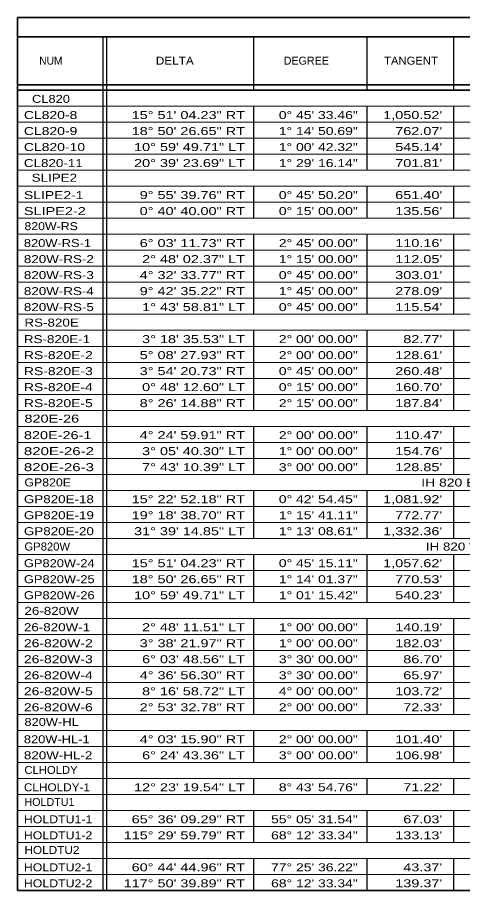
# Model space of a CAD drawing. Extents: x 1953053 to 1967065, y 7363860 to 7371201.
# Drawn here: x 1961966 to 1962633, y 7368856 to 7370165 of the extents above; entities that cross this region are included whole.
import ezdxf
from ezdxf.enums import TextEntityAlignment as Align

# ---------------------------------------------------------------- set-up
doc = ezdxf.new("R2010")
doc.units = 0
doc.header["$LTSCALE"] = 4.8
doc.layers.add('10', color=7, linetype='Continuous')
doc.layers.add('12', color=7, linetype='Continuous', lineweight=25)

msp = doc.modelspace()

# ---------------------------------------------------------------- linework, layer by layer
at = {"layer": '12', "lineweight": 35}
for p, q in [((1963689.794, 7370164.879), (1961966.462, 7370164.879)), ((1961966.462, 7370164.879), (1961966.462, 7368855.748)), ((1961966.462, 7370136.079), (1963689.794, 7370136.079)), ((1961966.462, 7370064.079), (1963689.794, 7370064.079)), ((1961966.462, 7370055.746), (1963689.794, 7370055.746)), ((1961966.462, 7368855.748), (1963689.794, 7368855.748))]:
    msp.add_line(p, q, dxfattribs=at)
at = {"layer": '12'}
for p, q in [((1962094.307, 7370136.079), (1962094.307, 7368855.748)), ((1962099.794, 7370136.079), (1962099.794, 7368855.748)), ((1962319.794, 7370136.079), (1962319.794, 7370055.746)), ((1962489.794, 7370136.079), (1962489.794, 7370055.746)), ((1962619.794, 7370136.079), (1962619.794, 7370055.746)), ((1962094.307, 7370114.479), (1962094.307, 7369766.526)), ((1962319.794, 7370031.746), (1962319.794, 7369935.746)), ((1962489.794, 7370031.746), (1962489.794, 7369935.746)), ((1962619.794, 7370031.746), (1962619.794, 7369935.746)), ((1962319.794, 7369911.746), (1962319.794, 7369863.746)), ((1962489.794, 7369911.746), (1962489.794, 7369863.746)), ((1962619.794, 7369911.746), (1962619.794, 7369863.746)), ((1962319.794, 7369839.746), (1962319.794, 7369719.746)), ((1962489.794, 7369839.746), (1962489.794, 7369719.746)), ((1962619.794, 7369839.746), (1962619.794, 7369719.746)), ((1962319.794, 7369695.746), (1962319.794, 7369575.746)), ((1962489.794, 7369695.746), (1962489.794, 7369575.746)), ((1962619.794, 7369695.746), (1962619.794, 7369575.746)), ((1962319.794, 7369551.746), (1962319.794, 7369479.746)), ((1962489.794, 7369551.746), (1962489.794, 7369479.746)), ((1962619.794, 7369551.746), (1962619.794, 7369479.746)), ((1962319.794, 7369455.746), (1962319.794, 7369383.746)), ((1962489.794, 7369455.746), (1962489.794, 7369383.746)), ((1962619.794, 7369455.746), (1962619.794, 7369383.746)), ((1962319.794, 7369359.746), (1962319.794, 7369287.746)), ((1962489.794, 7369359.746), (1962489.794, 7369287.746)), ((1962619.794, 7369359.746), (1962619.794, 7369287.746)), ((1962319.794, 7369263.746), (1962319.794, 7369119.746)), ((1962489.794, 7369263.746), (1962489.794, 7369119.746)), ((1962619.794, 7369263.746), (1962619.794, 7369119.746)), ((1962319.794, 7369095.746), (1962319.794, 7369047.747)), ((1962489.794, 7369095.746), (1962489.794, 7369047.747)), ((1962619.794, 7369095.746), (1962619.794, 7369047.747)), ((1962319.794, 7369023.747), (1962319.794, 7368999.747)), ((1962489.794, 7369023.747), (1962489.794, 7368999.747)), ((1962619.794, 7369023.747), (1962619.794, 7368999.747)), ((1962319.794, 7368975.747), (1962319.794, 7368927.747)), ((1962489.794, 7368975.747), (1962489.794, 7368927.747)), ((1962619.794, 7368975.747), (1962619.794, 7368927.747)), ((1962319.794, 7368903.747), (1962319.794, 7368855.747)), ((1962489.794, 7368903.747), (1962489.794, 7368855.747)), ((1962619.794, 7368903.747), (1962619.794, 7368855.747))]:
    msp.add_line(p, q, dxfattribs=at)
at = {"layer": '12', "lineweight": 13}
for p, q in [((1961966.462, 7370031.746), (1963689.794, 7370031.746)), ((1961966.462, 7370007.746), (1963689.794, 7370007.746)), ((1961966.462, 7369983.746), (1963689.794, 7369983.746)), ((1961966.462, 7369959.746), (1963689.794, 7369959.746)), ((1961966.462, 7369935.746), (1963689.794, 7369935.746)), ((1961966.462, 7369911.746), (1963689.794, 7369911.746)), ((1961966.462, 7369887.746), (1963689.794, 7369887.746)), ((1961966.462, 7369863.746), (1963689.794, 7369863.746)), ((1961966.462, 7369839.746), (1963689.794, 7369839.746)), ((1961966.462, 7369815.746), (1963689.794, 7369815.746)), ((1961966.462, 7369791.746), (1963689.794, 7369791.746)), ((1961966.462, 7369767.746), (1963689.794, 7369767.746)), ((1961966.462, 7369743.746), (1963689.794, 7369743.746)), ((1961966.462, 7369719.746), (1963689.794, 7369719.746)), ((1961966.462, 7369695.746), (1963689.794, 7369695.746)), ((1961966.462, 7369671.746), (1963689.794, 7369671.746)), ((1961966.462, 7369647.746), (1963689.794, 7369647.746)), ((1961966.462, 7369623.746), (1963689.794, 7369623.746)), ((1961966.462, 7369599.746), (1963689.794, 7369599.746)), ((1961966.462, 7369575.746), (1963689.794, 7369575.746)), ((1961966.462, 7369527.746), (1963689.794, 7369527.746)), ((1961966.462, 7369503.746), (1963689.794, 7369503.746)), ((1961966.462, 7369479.746), (1963689.794, 7369479.746)), ((1961966.462, 7369455.746), (1963689.794, 7369455.746)), ((1961966.462, 7369431.746), (1963689.794, 7369431.746)), ((1961966.462, 7369407.746), (1963689.794, 7369407.746)), ((1961966.462, 7369383.746), (1963689.794, 7369383.746)), ((1961966.462, 7369359.746), (1963689.794, 7369359.746)), ((1961966.462, 7369335.746), (1963689.794, 7369335.746)), ((1961966.462, 7369311.746), (1963689.794, 7369311.746)), ((1961966.462, 7369287.746), (1963689.794, 7369287.746)), ((1961966.462, 7369263.746), (1963689.794, 7369263.746)), ((1961966.462, 7369239.746), (1963689.794, 7369239.746)), ((1961966.462, 7369215.746), (1963689.794, 7369215.746)), ((1961966.462, 7369191.746), (1963689.794, 7369191.746)), ((1961966.462, 7369167.746), (1963689.794, 7369167.746)), ((1961966.462, 7369143.746), (1963689.794, 7369143.746)), ((1961966.462, 7369119.746), (1963689.794, 7369119.746)), ((1961966.462, 7369095.746), (1963689.794, 7369095.746)), ((1961966.462, 7369071.746), (1963689.794, 7369071.746)), ((1961966.462, 7369047.747), (1963689.794, 7369047.747)), ((1961966.462, 7369023.747), (1963689.794, 7369023.747)), ((1961966.462, 7368999.747), (1963689.794, 7368999.747)), ((1961966.462, 7368975.747), (1963689.794, 7368975.747)), ((1961966.462, 7368951.747), (1963689.794, 7368951.747)), ((1961966.462, 7368927.748), (1963689.794, 7368927.748)), ((1961966.462, 7368903.748), (1963689.794, 7368903.748)), ((1961966.462, 7368879.748), (1963689.794, 7368879.748))]:
    msp.add_line(p, q, dxfattribs=at)
msp.add_lwpolyline([(1961966.462, 7369551.746), (1962489.198, 7369551.746), (1963689.794, 7369551.746)], dxfattribs=at)

# ---------------------------------------------------------------- texts
at = {"layer": '10'}
for s, width, p in [('CL820', 1.2, (1961988.304, 7370036.747)), ('CL820-8', 1.3, (1961976.083, 7370012.573)), ('CL820-9', 1.3, (1961976.083, 7369988.573)), ('CL820-10', 1.3, (1961976.083, 7369964.573)), ('CL820-11', 1.25, (1961976.083, 7369940.573)), ('SLIPE2', 1.25, (1961987.746, 7369918.56)), ('SLIPE2-1', 1.3, (1961976.083, 7369892.573)), ('SLIPE2-2', 1.35, (1961976.083, 7369868.573)), ('820W-RS', 1.15, (1961976.893, 7369845.942)), ('820W-RS-1', 1.2, (1961976.083, 7369820.573)), ('820W-RS-2', 1.25, (1961976.083, 7369796.573)), ('820W-RS-3', 1.25, (1961976.083, 7369772.573)), ('820W-RS-4', 1.25, (1961976.083, 7369748.573)), ('820W-RS-5', 1.25, (1961976.083, 7369724.573)), ('RS-820E', 1.25, (1961976.893, 7369701.35)), ('RS-820E-1', 1.25, (1961976.083, 7369676.573)), ('RS-820E-2', 1.3, (1961976.083, 7369652.573)), ('RS-820E-3', 1.3, (1961976.083, 7369628.573)), ('RS-820E-4', 1.3, (1961976.083, 7369604.573)), ('RS-820E-5', 1.3, (1961976.083, 7369580.573)), ('820E-26', 1.35, (1961976.893, 7369557.348)), ('820E-26-1', 1.35, (1961976.083, 7369532.573)), ('820E-26-2', 1.4, (1961976.083, 7369508.573)), ('820E-26-3', 1.4, (1961976.083, 7369484.573)), ('GP820E', 1.15, (1961976.893, 7369461.712)), ('GP820E-18', 1.25, (1961976.083, 7369436.573)), ('GP820E-19', 1.25, (1961976.083, 7369412.573)), ('GP820E-20', 1.25, (1961976.083, 7369388.573)), ('GP820W', 1.05, (1961976.893, 7369365.605)), ('GP820W-24', 1.2, (1961976.083, 7369340.573)), ('GP820W-25', 1.2, (1961976.083, 7369316.573)), ('GP820W-26', 1.2, (1961976.083, 7369292.573)), ('26-820W', 1.25, (1961976.893, 7369269.117)), ('26-820W-1', 1.25, (1961976.083, 7369244.573)), ('26-820W-2', 1.3, (1961976.083, 7369220.573)), ('26-820W-3', 1.3, (1961976.083, 7369196.573)), ('26-820W-4', 1.3, (1961976.083, 7369172.573)), ('26-820W-5', 1.3, (1961976.083, 7369148.573)), ('26-820W-6', 1.3, (1961976.083, 7369124.573)), ('820W-HL', 1.2, (1961976.893, 7369102.55)), ('820W-HL-1', 1.2, (1961976.083, 7369076.573)), ('820W-HL-2', 1.25, (1961976.083, 7369052.573)), ('CLHOLDY', 1.05, (1961976.893, 7369030.551)), ('CLHOLDY-1', 1.1, (1961976.083, 7369004.574)), ('HOLDTU1-1', 1.15, (1961976.083, 7368956.574)), ('HOLDTU1-2', 1.15, (1961976.083, 7368932.574)), ('HOLDTU2', 1.1, (1961976.893, 7368910.552)), ('HOLDTU2-1', 1.15, (1961976.083, 7368884.575)), ('HOLDTU2-2', 1.15, (1961976.083, 7368860.575))]:
    msp.add_text(s, height=12, dxfattribs=dict(at, width=width)).set_placement(p)
for s, width, p in [('15° 51\' 04.23" RT', 1.35, (1962307.316, 7370012.573)), ('0° 45\' 33.46"', 1.3, (1962476.311, 7370012.573)), ("1,050.52'", 1.35, (1962602.721, 7370012.573)), ('18° 50\' 26.65" RT', 1.35, (1962307.316, 7369988.573)), ('1° 14\' 50.69"', 1.3, (1962476.311, 7369988.573)), ("762.07'", 1.35, (1962602.721, 7369988.573)), ('10° 59\' 49.71" LT', 1.35, (1962307.316, 7369964.573)), ('1° 00\' 42.32"', 1.3, (1962476.311, 7369964.573)), ("545.14'", 1.35, (1962602.721, 7369964.573)), ('20° 39\' 23.69" LT', 1.35, (1962307.316, 7369940.573)), ('1° 29\' 16.14"', 1.3, (1962476.311, 7369940.573)), ("701.81'", 1.35, (1962602.721, 7369940.573)), ('9° 55\' 39.76" RT', 1.35, (1962307.316, 7369892.573)), ('0° 45\' 50.20"', 1.3, (1962476.311, 7369892.573)), ("651.40'", 1.35, (1962602.721, 7369892.573)), ('0° 40\' 40.00" RT', 1.35, (1962307.316, 7369868.573)), ('0° 15\' 00.00"', 1.3, (1962476.311, 7369868.573)), ("135.56'", 1.35, (1962602.721, 7369868.573)), ('6° 03\' 11.73" RT', 1.35, (1962307.316, 7369820.573)), ('2° 45\' 00.00"', 1.3, (1962476.311, 7369820.573)), ("110.16'", 1.35, (1962602.721, 7369820.573)), ('2° 48\' 02.37" LT', 1.35, (1962307.316, 7369796.573)), ('1° 15\' 00.00"', 1.3, (1962476.311, 7369796.573)), ("112.05'", 1.35, (1962602.721, 7369796.573)), ('4° 32\' 33.77" RT', 1.35, (1962307.316, 7369772.573)), ('0° 45\' 00.00"', 1.3, (1962476.311, 7369772.573)), ("303.01'", 1.35, (1962602.721, 7369772.573)), ('9° 42\' 35.22" RT', 1.35, (1962307.316, 7369748.573)), ('1° 45\' 00.00"', 1.3, (1962476.311, 7369748.573)), ("278.09'", 1.35, (1962602.721, 7369748.573)), ('1° 43\' 58.81" LT', 1.35, (1962307.316, 7369724.573)), ('0° 45\' 00.00"', 1.3, (1962476.311, 7369724.573)), ("115.54'", 1.35, (1962602.721, 7369724.573)), ('3° 18\' 35.53" LT', 1.35, (1962307.316, 7369676.573)), ('2° 00\' 00.00"', 1.3, (1962476.311, 7369676.573)), ("82.77'", 1.35, (1962602.721, 7369676.573)), ('5° 08\' 27.93" RT', 1.35, (1962307.316, 7369652.573)), ('2° 00\' 00.00"', 1.3, (1962476.311, 7369652.573)), ("128.61'", 1.35, (1962602.721, 7369652.573)), ('3° 54\' 20.73" RT', 1.35, (1962307.316, 7369628.573)), ('0° 45\' 00.00"', 1.3, (1962476.311, 7369628.573)), ("260.48'", 1.35, (1962602.721, 7369628.573)), ('0° 48\' 12.60" LT', 1.35, (1962307.316, 7369604.573)), ('0° 15\' 00.00"', 1.3, (1962476.311, 7369604.573)), ("160.70'", 1.35, (1962602.721, 7369604.573)), ('8° 26\' 14.88" RT', 1.35, (1962307.316, 7369580.573)), ('2° 15\' 00.00"', 1.3, (1962476.311, 7369580.573)), ("187.84'", 1.35, (1962602.721, 7369580.573)), ('4° 24\' 59.91" RT', 1.35, (1962307.316, 7369532.573)), ('2° 00\' 00.00"', 1.3, (1962476.311, 7369532.573)), ("110.47'", 1.35, (1962602.721, 7369532.573)), ('3° 05\' 40.30" LT', 1.35, (1962307.316, 7369508.573)), ('1° 00\' 00.00"', 1.3, (1962476.311, 7369508.573)), ("154.76'", 1.35, (1962602.721, 7369508.573)), ('7° 43\' 10.39" LT', 1.35, (1962307.316, 7369484.573)), ('3° 00\' 00.00"', 1.3, (1962476.311, 7369484.573)), ("128.85'", 1.35, (1962602.721, 7369484.573)), ('15° 22\' 52.18" RT', 1.35, (1962307.316, 7369436.573)), ('0° 42\' 54.45"', 1.3, (1962476.311, 7369436.573)), ("1,081.92'", 1.35, (1962602.721, 7369436.573)), ('19° 18\' 38.70" RT', 1.35, (1962307.316, 7369412.573)), ('1° 15\' 41.11"', 1.3, (1962476.311, 7369412.573)), ("772.77'", 1.35, (1962602.721, 7369412.573)), ('31° 39\' 14.85" LT', 1.35, (1962307.316, 7369388.573)), ('1° 13\' 08.61"', 1.3, (1962476.311, 7369388.573)), ("1,332.36'", 1.35, (1962602.721, 7369388.573)), ('15° 51\' 04.23" RT', 1.35, (1962307.316, 7369340.573)), ('0° 45\' 15.11"', 1.3, (1962476.311, 7369340.573)), ("1,057.62'", 1.35, (1962602.721, 7369340.573)), ('18° 50\' 26.65" RT', 1.35, (1962307.316, 7369316.573)), ('1° 14\' 01.37"', 1.3, (1962476.311, 7369316.573)), ("770.53'", 1.35, (1962602.721, 7369316.573)), ('10° 59\' 49.71" LT', 1.35, (1962307.316, 7369292.573)), ('1° 01\' 15.42"', 1.3, (1962476.311, 7369292.573)), ("540.23'", 1.35, (1962602.721, 7369292.573)), ('2° 48\' 11.51" LT', 1.35, (1962307.316, 7369244.573)), ('1° 00\' 00.00"', 1.3, (1962476.311, 7369244.573)), ("140.19'", 1.35, (1962602.721, 7369244.573)), ('3° 38\' 21.97" RT', 1.35, (1962307.316, 7369220.573)), ('1° 00\' 00.00"', 1.3, (1962476.311, 7369220.573)), ("182.03'", 1.35, (1962602.721, 7369220.573)), ('6° 03\' 48.56" LT', 1.35, (1962307.316, 7369196.573)), ('3° 30\' 00.00"', 1.3, (1962476.311, 7369196.573)), ("86.70'", 1.35, (1962602.721, 7369196.573)), ('4° 36\' 56.30" RT', 1.35, (1962307.316, 7369172.573)), ('3° 30\' 00.00"', 1.3, (1962476.311, 7369172.573)), ("65.97'", 1.35, (1962602.721, 7369172.573)), ('8° 16\' 58.72" LT', 1.35, (1962307.316, 7369148.573)), ('4° 00\' 00.00"', 1.3, (1962476.311, 7369148.573)), ("103.72'", 1.35, (1962602.721, 7369148.573)), ('2° 53\' 32.78" RT', 1.35, (1962307.316, 7369124.573)), ('2° 00\' 00.00"', 1.3, (1962476.311, 7369124.573)), ("72.33'", 1.35, (1962602.721, 7369124.573)), ('4° 03\' 15.90" RT', 1.35, (1962307.316, 7369076.573)), ('2° 00\' 00.00"', 1.3, (1962476.311, 7369076.573)), ("101.40'", 1.35, (1962602.721, 7369076.573)), ('6° 24\' 43.36" LT', 1.35, (1962307.316, 7369052.573)), ('3° 00\' 00.00"', 1.3, (1962476.311, 7369052.573)), ("106.98'", 1.35, (1962602.721, 7369052.573)), ('12° 23\' 19.54" LT', 1.35, (1962307.316, 7369004.574)), ('8° 43\' 54.76"', 1.3, (1962476.311, 7369004.574)), ("71.22'", 1.35, (1962602.721, 7369004.574)), ('65° 36\' 09.29" RT', 1.35, (1962307.316, 7368956.574)), ('55° 05\' 31.54"', 1.3, (1962476.311, 7368956.574)), ("67.03'", 1.35, (1962602.721, 7368956.574)), ('115° 29\' 59.79" RT', 1.35, (1962307.316, 7368932.574)), ('68° 12\' 33.34"', 1.3, (1962476.311, 7368932.574)), ("133.13'", 1.35, (1962602.721, 7368932.574)), ('60° 44\' 44.96" RT', 1.35, (1962307.316, 7368884.575)), ('77° 25\' 36.22"', 1.3, (1962476.311, 7368884.575)), ("43.37'", 1.35, (1962602.721, 7368884.575)), ('117° 50\' 39.89" RT', 1.35, (1962307.316, 7368860.575)), ('68° 12\' 33.34"', 1.3, (1962476.311, 7368860.575)), ("139.37'", 1.35, (1962602.721, 7368860.575))]:
    msp.add_text(s, height=12, dxfattribs=dict(at, width=width)).set_placement(p, align=Align.RIGHT)
for s, width, p in [('IH 820 EB GENERAL PURPOSE MAIN LANES BASELINE (GP820E)', 1.3, (1962894.795, 7369461.54)), ('IH 820 WB GENERAL PURPOSE MAIN LANES BASELINE (GP820W)', 1.25, (1962894.795, 7369365.54))]:
    msp.add_text(s, height=12, dxfattribs=dict(at, width=width)).set_placement(p, align=Align.CENTER)
msp.add_text('HOLDTU1', height=12, dxfattribs=at).set_placement((1961976.893, 7368982.551))
at = {"layer": '12'}
for s, width, p in [('NUM', 0.95, (1962016.508, 7370094.075)), ('DELTA', 1.1, (1962202.085, 7370094.078)), ('TANGENT', 1.05, (1962555.982, 7370094.078))]:
    msp.add_text(s, height=12, dxfattribs=dict(at, width=width)).set_placement(p, align=Align.CENTER)
msp.add_text('DEGREE', height=12, dxfattribs=at).set_placement((1962399.171, 7370094.078), align=Align.CENTER)

doc.saveas('drawing.dxf')
